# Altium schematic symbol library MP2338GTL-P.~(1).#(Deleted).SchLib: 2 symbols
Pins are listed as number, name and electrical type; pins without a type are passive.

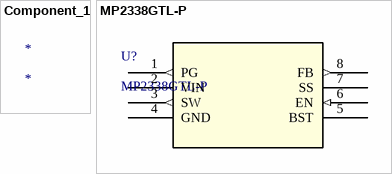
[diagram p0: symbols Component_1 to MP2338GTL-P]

## Component_1
designator *

## MP2338GTL-P
designator U?
High-Efficiency 28V 3A 450kHz Synchronous Step-Down Converter In SOT583 Package; Manufacturer_Name: Monolithic Power Systems
footprint SOT583_MP2338_MNP
pins: 1 PG (out), 2 VIN (power), 3 SW (out), 4 GND (power), 5 BST (power), 6 EN (in), 7 SS, 8 FB (out)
